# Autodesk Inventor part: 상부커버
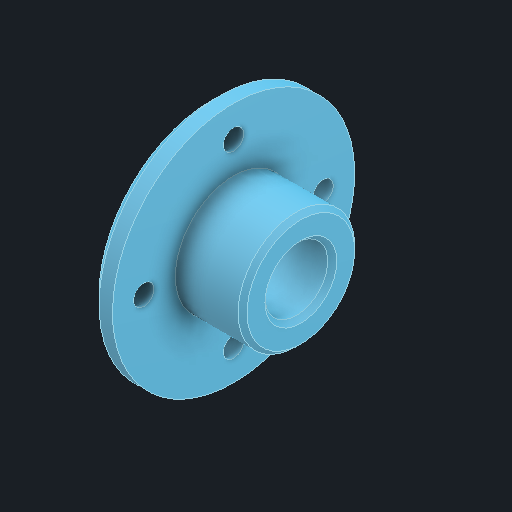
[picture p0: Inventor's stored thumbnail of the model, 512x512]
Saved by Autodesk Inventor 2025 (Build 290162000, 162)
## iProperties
Created: 2025-08
Part Number: 상부커버
Material: 알루미늄 6061
Document SubType Name: Modeling
Designer: infra006
Density: 2.71 g/cm^3
Appearance: 기본값
Author: jhkim
Sending System: Autodesk Inventor 2026
Preprocessor: ST-DEVELOPER v20.1
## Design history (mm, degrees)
feature "솔리드1"
node "솔리드2"
